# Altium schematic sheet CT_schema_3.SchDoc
size 300 x 163 mm
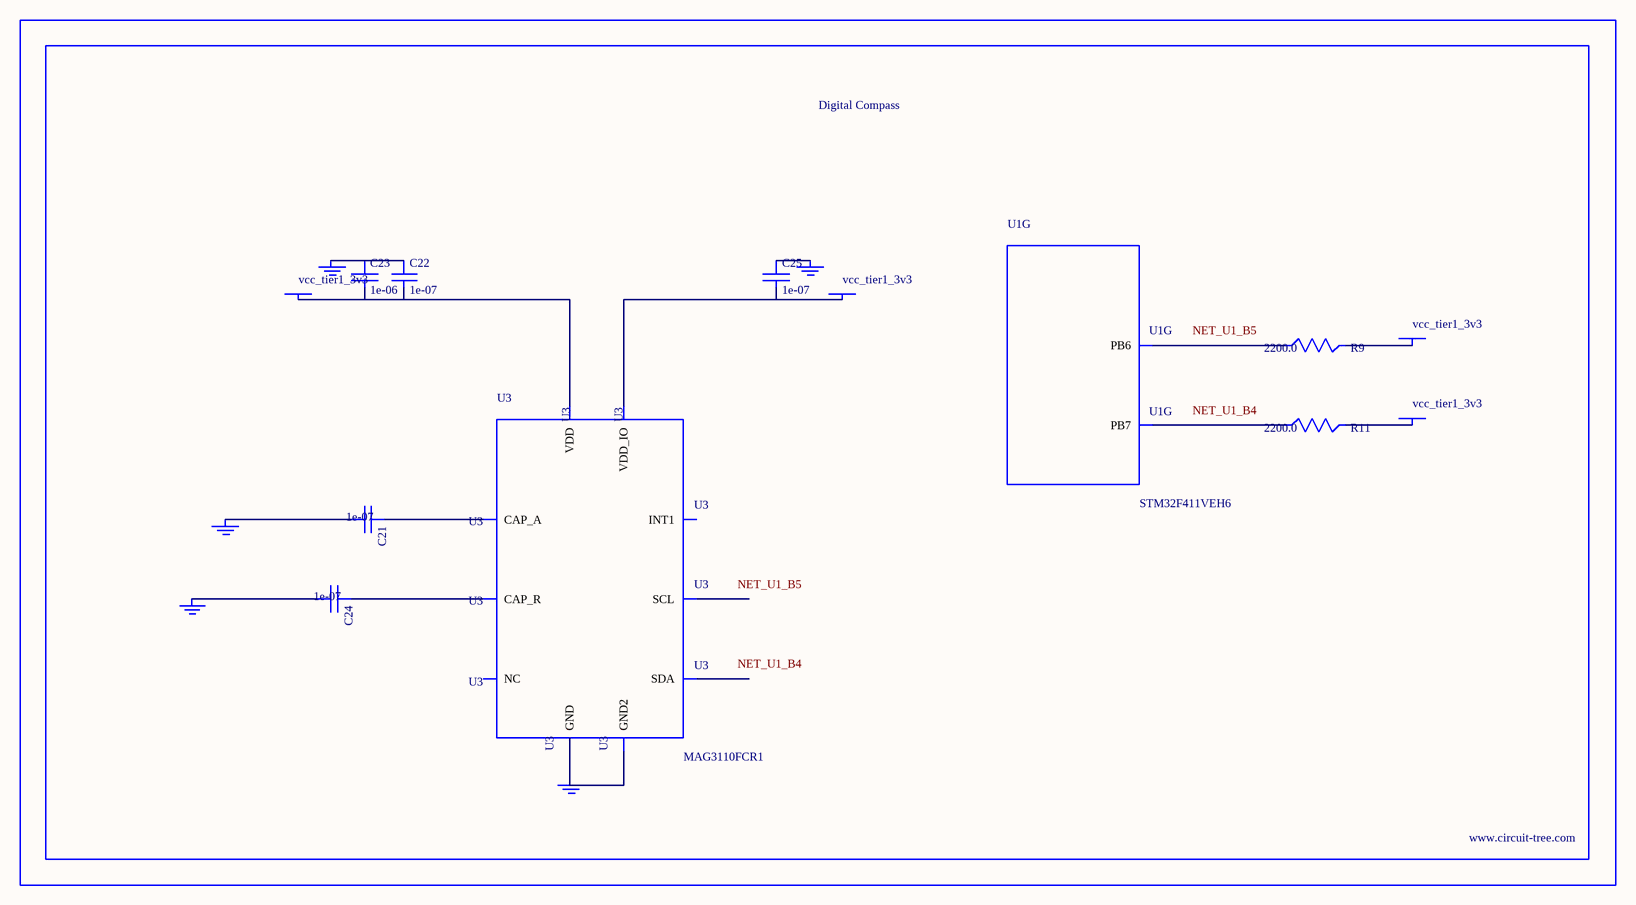
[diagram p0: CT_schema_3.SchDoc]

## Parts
BORDER2  (no value)
C21  1e-07  [C0402]
C22  1e-07  [C0402]
C23  1e-06  [C0603]
C24  1e-07  [C0402]
C25  1e-07  [C0402]
GND_INSTANCE_2_0  (no value)
GND_INSTANCE_2_1  (no value)
GND_INSTANCE_2_2  (no value)
GND_INSTANCE_2_3  (no value)
GND_INSTANCE_2_4  (no value)
POWER_INSTANCE_2_0  vcc_tier1_3v3
POWER_INSTANCE_2_1  vcc_tier1_3v3
POWER_INSTANCE_2_2  vcc_tier1_3v3
POWER_INSTANCE_2_3  vcc_tier1_3v3
R9  2200.0  [R0603]
R11  2200.0  [R0603]
U1  STM32F411VEH6  [UFBGA100]  (part G of 8)
U3  MAG3110FCR1  [DFN-10]

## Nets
NetC21_1: C21.1 U3.1(CAP_A)
NetC21_2: C21.2 GND_INSTANCE_2_0.0(GND)
NetC22_1: C22.1 C23.1 GND_INSTANCE_2_1.0(GND)
NetC22_2: C22.2 C23.2 POWER_INSTANCE_2_0.0(PWR) U3.2(VDD)
NetC24_1: C24.1 U3.4(CAP_R)
NetC24_2: C24.2 GND_INSTANCE_2_2.0(GND)
NetC25_1: C25.1 GND_INSTANCE_2_3.0(GND)
NetC25_2: C25.2 POWER_INSTANCE_2_1.0(PWR) U3.8(VDD_IO)
NetGND_INSTANCE_2_4_0: GND_INSTANCE_2_4.0(GND) U3.5(GND) U3.10(GND2)
NetPOWER_INSTANCE_2_2_0: POWER_INSTANCE_2_2.0(PWR) R9.2
NetPOWER_INSTANCE_2_3_0: POWER_INSTANCE_2_3.0(PWR) R11.2
NetR9_1: R9.1 U1.B5(PB6)
NetR11_1: R11.1 U1.B4(PB7)

Not connected (* = marked no-connect by the designer): U3 3(NC) 6(SDA) 7(SCL) 9(INT1)

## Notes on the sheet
- Labels drawn without touching a wire or pin: NET_U1_B4, NET_U1_B5

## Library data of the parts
BORDER2 = BORDER_PAGE2
C21 C22 C24 C25 = C0402C104K3RACTU
C23 = C0603C105K3RACTU
GND_INSTANCE_2_0-GND_INSTANCE_2_4 = GND
POWER_INSTANCE_2_0-POWER_INSTANCE_2_3 = PWR
R9 R11 = RC0603JR-072K2L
